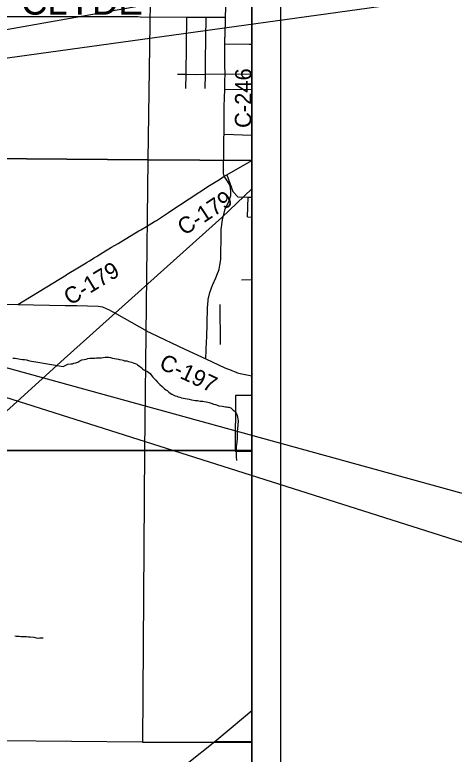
# Model space of a CAD drawing. Extents: x 36.7 to 70.7, y 0 to 22.
# Drawn here: x 44.771 to 46.296, y 14.842 to 17.404 of the extents above; entities that cross this region are included whole.
import ezdxf

# ---------------------------------------------------------------- set-up
doc = ezdxf.new("R2010")
doc.units = 0
for name, color, linetype in [('Default', 7, 'Continuous'), ('GM_X_City_Street', 7, 'Continuous'), ('GM_X_Corporation_Text', 7, 'Continuous'), ('GM_X_County_Road', 7, 'Continuous'), ('GM_X_County_Road_Text', 7, 'Continuous'), ('GM_X_Minor_River', 7, 'Continuous'), ('GM_X_Rail_Line', 7, 'Continuous'), ('GM_X_Section', 7, 'Continuous'), ('GM_X_Township_Road', 7, 'Continuous'), ('SH_Data', 7, 'Continuous'), ('SH_Text', 7, 'Continuous')]:
    doc.layers.add(name, color=color, linetype=linetype)

msp = doc.modelspace()

# ---------------------------------------------------------------- linework, layer by layer
at = {"layer": 'Default'}
for points in [[(45.5934, 16.8994), (45.5934, 17.918), (45.2484, 17.9213), (45.2325, 16.9015)], [(45.5934, 15.8939), (45.5934, 16.8994), (45.2325, 16.9015), (45.2216, 15.8945)], [(45.5934, 15.8922), (45.5934, 16.0849), (45.5377, 16.0855), (45.5361, 15.8922)], [(45.5934, 14.8831), (45.5934, 15.8939), (45.2216, 15.8945), (45.2149, 14.8834)]]:
    msp.add_lwpolyline(points, close=True, dxfattribs=at)
at = {"layer": 'GM_X_City_Street'}
for p, q in [((45.5008, 17.1995), (45.5934, 17.1983)), ((45.4999, 17.1457), (45.5934, 17.1462)), ((45.4973, 16.9912), (45.5934, 16.9874)), ((45.5786, 16.7037), (45.5811, 16.7728)), ((45.5786, 16.7037), (45.5934, 16.7035)), ((45.5576, 16.4863), (45.5934, 16.4872)), ((45.4849, 16.2621), (45.4842, 16.4))]:
    msp.add_line(p, q, dxfattribs=at)
for points in [[(45.5, 17.304), (45.5851, 17.3029), (45.5934, 17.303)], [(45.5071, 16.8503), (45.5273, 16.7919), (45.5453, 16.773), (45.5811, 16.7728), (45.5934, 16.7727)]]:
    msp.add_lwpolyline(points, dxfattribs=at)
at = {"layer": 'GM_X_County_Road'}
for p, q in [((45.503, 17.3961), (45.5047, 17.4867)), ((45.206, 17.3979), (45.3682, 17.3965)), ((45.5001, 17.3079), (45.5007, 17.3272)), ((45.4811, 16.834), (45.498, 16.8448)), ((45.4472, 16.8123), (45.4811, 16.834)), ((45.2625, 16.6919), (45.3048, 16.7195)), ((45.185, 16.6452), (45.2023, 16.6555)), ((44.4801, 16.4056), (44.7825, 16.4)), ((44.7825, 16.4), (44.9458, 16.3971)), ((44.9458, 16.3971), (44.9765, 16.3965)), ((44.9765, 16.3965), (44.9867, 16.3964)), ((45.1238, 16.3677), (45.2305, 16.3081)), ((45.4342, 16.2122), (45.4367, 16.2722)), ((45.5441, 16.1638), (45.5532, 16.1611))]:
    msp.add_line(p, q, dxfattribs=at)
for points in [[(44.498, 17.4024), (44.7452, 17.3981), (45.1979, 17.398), (45.206, 17.3979)], [(45.3682, 17.3965), (45.4359, 17.3967), (45.503, 17.3961)], [(45.5007, 17.3272), (45.5008, 17.3282), (45.503, 17.3961)], [(45.4999, 17.2873), (45.4999, 17.2893), (45.5, 17.304), (45.5001, 17.3079)], [(45.5, 17.2286), (45.4999, 17.2306), (45.4996, 17.2413), (45.4999, 17.2873)], [(45.4999, 17.1497), (45.4999, 17.1526), (45.5002, 17.1742), (45.5008, 17.1995), (45.5, 17.2286)], [(45.4995, 17.1301), (45.4996, 17.133), (45.4999, 17.1457), (45.4999, 17.1497)], [(45.4971, 16.9727), (45.4972, 16.9776), (45.4973, 16.9912), (45.4982, 17.0726), (45.4995, 17.1301)], [(45.4965, 16.9334), (45.4969, 16.9581), (45.4971, 16.9727)], [(45.498, 16.8448), (45.4957, 16.8553), (45.4952, 16.8672), (45.4965, 16.9334)], [(45.498, 16.8448), (45.5071, 16.8503), (45.5934, 16.9)], [(45.478, 16.5164), (45.4799, 16.5223), (45.4831, 16.5366), (45.4862, 16.5559), (45.4868, 16.5846), (45.487, 16.6233), (45.4879, 16.6605), (45.4921, 16.6941), (45.501, 16.7316), (45.5142, 16.7561), (45.5213, 16.7784), (45.5213, 16.7928), (45.5185, 16.813), (45.5094, 16.828), (45.498, 16.8448)], [(45.3048, 16.7195), (45.3057, 16.7201), (45.4472, 16.8123)], [(45.2281, 16.671), (45.2566, 16.688), (45.2625, 16.6919)], [(45.2023, 16.6555), (45.2083, 16.6591), (45.2281, 16.671)], [(45.1075, 16.5986), (45.1299, 16.6121), (45.185, 16.6452)], [(45.0549, 16.5668), (45.0864, 16.5859), (45.098, 16.5929), (45.1075, 16.5986)], [(45.0307, 16.5521), (45.0472, 16.5621), (45.0549, 16.5668)], [(44.9533, 16.5053), (44.9902, 16.5276), (45.0195, 16.5453), (45.022, 16.5469)], [(45.022, 16.5469), (45.0229, 16.5474), (45.0307, 16.5521)], [(44.7825, 16.4), (44.9508, 16.5037), (44.9533, 16.5053)], [(45.4401, 16.3928), (45.4406, 16.3982), (45.4422, 16.4177), (45.4484, 16.4424), (45.4574, 16.467), (45.4584, 16.4692), (45.4689, 16.4923), (45.4751, 16.5075), (45.478, 16.5164)], [(44.9867, 16.3964), (45.0612, 16.395), (45.0687, 16.3938), (45.0763, 16.3925), (45.0911, 16.3859), (45.0967, 16.3828)], [(45.0967, 16.3828), (45.1095, 16.3756), (45.1238, 16.3677)], [(45.4367, 16.2722), (45.4372, 16.2855), (45.4396, 16.3862), (45.4401, 16.3928)], [(45.2305, 16.3081), (45.2322, 16.3071), (45.2399, 16.3032)], [(45.2399, 16.3032), (45.2448, 16.3008), (45.3609, 16.2452), (45.4342, 16.2122), (45.5006, 16.181), (45.5223, 16.1724), (45.5322, 16.1684), (45.5393, 16.1654), (45.5405, 16.1649), (45.5441, 16.1638)], [(45.5532, 16.1611), (45.5876, 16.1545), (45.5934, 16.1536)], [(44.5137, 14.0969), (44.61, 14.1895), (44.7503, 14.3191), (44.8652, 14.405), (44.9312, 14.4499), (45.0351, 14.527), (45.1075, 14.5955), (45.18, 14.6649), (45.3691, 14.8101), (45.4651, 14.8861), (45.5652, 14.9689), (45.5934, 14.9928)]]:
    msp.add_lwpolyline(points, dxfattribs=at)
at = {"layer": 'GM_X_Minor_River'}
for points in [[(44.7646, 16.2145), (44.7722, 16.2144), (44.7786, 16.2135), (44.7854, 16.2119), (44.79, 16.2111), (44.7979, 16.2103), (44.8055, 16.2095), (44.8119, 16.2086), (44.8187, 16.2067), (44.824, 16.2055), (44.8297, 16.2043), (44.8362, 16.2031), (44.8449, 16.2022), (44.9395, 16.1856)], [(44.9395, 16.1856), (44.9559, 16.194), (44.9658, 16.1952), (44.9722, 16.1952), (44.976, 16.1968), (44.9832, 16.1983), (44.9901, 16.201), (44.9972, 16.2048), (45.0041, 16.2083), (45.0116, 16.2102), (45.0185, 16.2114), (45.0245, 16.2133), (45.0317, 16.2149), (45.0382, 16.2149), (45.0446, 16.2146), (45.0488, 16.2142), (45.0545, 16.215), (45.0617, 16.2158), (45.0708, 16.2158), (45.0784, 16.2162), (45.0852, 16.2174), (45.0913, 16.2178), (45.0978, 16.2175), (45.1039, 16.2164), (45.1099, 16.2149), (45.1175, 16.2134), (45.1248, 16.2123), (45.1308, 16.2112), (45.135, 16.2097), (45.1426, 16.2086), (45.1472, 16.2071), (45.1521, 16.2056), (45.1559, 16.2052), (45.1601, 16.2049), (45.1658, 16.2034), (45.1711, 16.2019), (45.1761, 16.2004), (45.1818, 16.1981), (45.1886, 16.1959), (45.1943, 16.1932), (45.1985, 16.1906), (45.2038, 16.1868), (45.2099, 16.1819), (45.2137, 16.1797), (45.2149, 16.1759), (45.2217, 16.1725), (45.2316, 16.1687), (45.237, 16.165), (45.2415, 16.1608), (45.2461, 16.1544), (45.2507, 16.1487), (45.2549, 16.1441), (45.2606, 16.1377), (45.2664, 16.1317), (45.2713, 16.1271), (45.2748, 16.1233), (45.2831, 16.1158), (45.2873, 16.1116), (45.2912, 16.1082), (45.2957, 16.1048), (45.2995, 16.1018), (45.306, 16.0961), (45.3102, 16.0928), (45.3163, 16.0894), (45.3213, 16.0871), (45.3281, 16.0841), (45.3334, 16.0826), (45.3387, 16.0807), (45.3437, 16.0792), (45.3494, 16.0774), (45.3562, 16.0759), (45.3627, 16.0744), (45.3699, 16.0729), (45.3767, 16.0718), (45.3843, 16.0703), (45.3916, 16.0692), (45.3976, 16.0681), (45.4052, 16.0674), (45.4144, 16.0659), (45.4185, 16.0655), (45.4235, 16.0652), (45.4284, 16.0644), (45.4349, 16.063), (45.4406, 16.0618), (45.4463, 16.0604), (45.4558, 16.057), (45.4611, 16.0551), (45.4672, 16.0536), (45.4714, 16.0525), (45.4794, 16.0491), (45.4907, 16.0476), (45.4961, 16.0465), (45.5021, 16.0462), (45.5063, 16.0458), (45.5101, 16.0447), (45.5143, 16.044), (45.5204, 16.0417), (45.5253, 16.0376), (45.5295, 16.0345), (45.536, 16.0293), (45.5387, 16.0255)], [(45.5387, 16.0255), (45.541, 16.0217), (45.5429, 16.016), (45.5445, 16.0095), (45.5456, 16.0027), (45.546, 15.9985), (45.5464, 15.9921), (45.5457, 15.9864), (45.5457, 15.9814), (45.5443, 15.9734), (45.5435, 15.9674), (45.5428, 15.9624), (45.5424, 15.9571), (45.5425, 15.9506), (45.5429, 15.9431), (45.5429, 15.9374), (45.5426, 15.9328), (45.5422, 15.9271), (45.5419, 15.9218), (45.5404, 15.9149), (45.5393, 15.9081), (45.5393, 15.9016), (45.5397, 15.8978), (45.5397, 15.8933), (45.5394, 15.8861), (45.539, 15.8792), (45.5391, 15.869), (45.5403, 15.864), (45.5407, 15.8602)], [(44.7711, 15.2517), (44.7768, 15.2512), (44.7813, 15.2508), (44.787, 15.2504), (44.7919, 15.2503), (44.7991, 15.2495), (44.8116, 15.2493), (44.8185, 15.2489), (44.8249, 15.2488), (44.8378, 15.2472), (44.8461, 15.2456), (44.8525, 15.2443), (44.8582, 15.2447), (44.8651, 15.2454), (44.87, 15.2457)]]:
    msp.add_lwpolyline(points, dxfattribs=at)
at = {"layer": 'GM_X_Rail_Line'}
msp.add_lwpolyline([(42.5932, 14.0969), (42.6018, 14.1045), (42.9057, 14.3723), (43.2092, 14.6439), (43.5174, 14.9236), (43.8818, 15.2533), (44.2007, 15.5398), (44.9423, 16.2118), (45.4899, 16.7019), (45.5934, 16.801)], dxfattribs=at)
at = {"layer": 'GM_X_Section'}
for points in [[(45.2484, 17.9213), (45.2325, 16.9015), (44.2493, 16.9097), (44.2567, 17.9094)], [(45.2325, 16.9015), (45.2216, 15.8945), (44.2362, 15.8944), (44.2493, 16.9097)], [(45.2216, 15.8945), (45.2149, 14.8834), (44.2284, 14.8924), (44.2362, 15.8944)]]:
    msp.add_lwpolyline(points, close=True, dxfattribs=at)
at = {"layer": 'GM_X_Township_Road'}
for p, q in [((45.3361, 17.1991), (45.3649, 17.1987)), ((45.4651, 14.8861), (45.5934, 14.8863))]:
    msp.add_line(p, q, dxfattribs=at)
for points in [[(45.5934, 14.0969), (45.5934, 19.8832)], [(45.3644, 17.1489), (45.3659, 17.1987), (45.3682, 17.3965)], [(45.4335, 17.2287), (45.4336, 17.2465), (45.4359, 17.3967)], [(45.4321, 17.1493), (45.4332, 17.1991), (45.4335, 17.2287)], [(45.3649, 17.1987), (45.3659, 17.1987), (45.3984, 17.1979), (45.4332, 17.1991), (45.5008, 17.1995)]]:
    msp.add_lwpolyline(points, dxfattribs=at)
at = {"layer": 'SH_Data'}
for p, q in [((45.6934, 20.9969), (45.6934, 13.9969)), ((45.5934, 20.8969), (45.5934, 14.0969))]:
    msp.add_line(p, q, dxfattribs=at)
at = {"layer": 'SH_Text'}
for points in [[(47.1799, 17.7861), (42.2435, 16.9102), (47.1799, 17.5925)], [(42.2513, 16.8669), (47.0528, 15.5458), (47.0528, 15.3449)]]:
    msp.add_lwpolyline(points, close=True, dxfattribs=at)

# ---------------------------------------------------------------- texts
at = {"layer": 'GM_X_Corporation_Text'}
msp.add_text('CLYDE', height=0.0947, rotation=0, dxfattribs=at).set_placement((44.7931, 17.4049))
at = {"layer": 'GM_X_County_Road_Text'}
for s, rotation, p in [('C-246', 89.7233, (45.5917, 17.012)), ('C-179', 33.1867, (45.3595, 16.6376)), ('C-179', 31.4252, (44.9635, 16.3956)), ('C-197', 335.0307, (45.2685, 16.1804))]:
    msp.add_text(s, height=0.05682, rotation=rotation, dxfattribs=at).set_placement(p)

doc.saveas('drawing.dxf')
